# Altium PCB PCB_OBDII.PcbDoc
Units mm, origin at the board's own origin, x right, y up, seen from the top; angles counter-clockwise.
Board outline 98.69 x 84.64 mm, 2 copper layers (F.Cu, B.Cu); 8 components, 39 nets, 74 pads, 0 vias.
Unrouted connection lines stored in the file: 5.
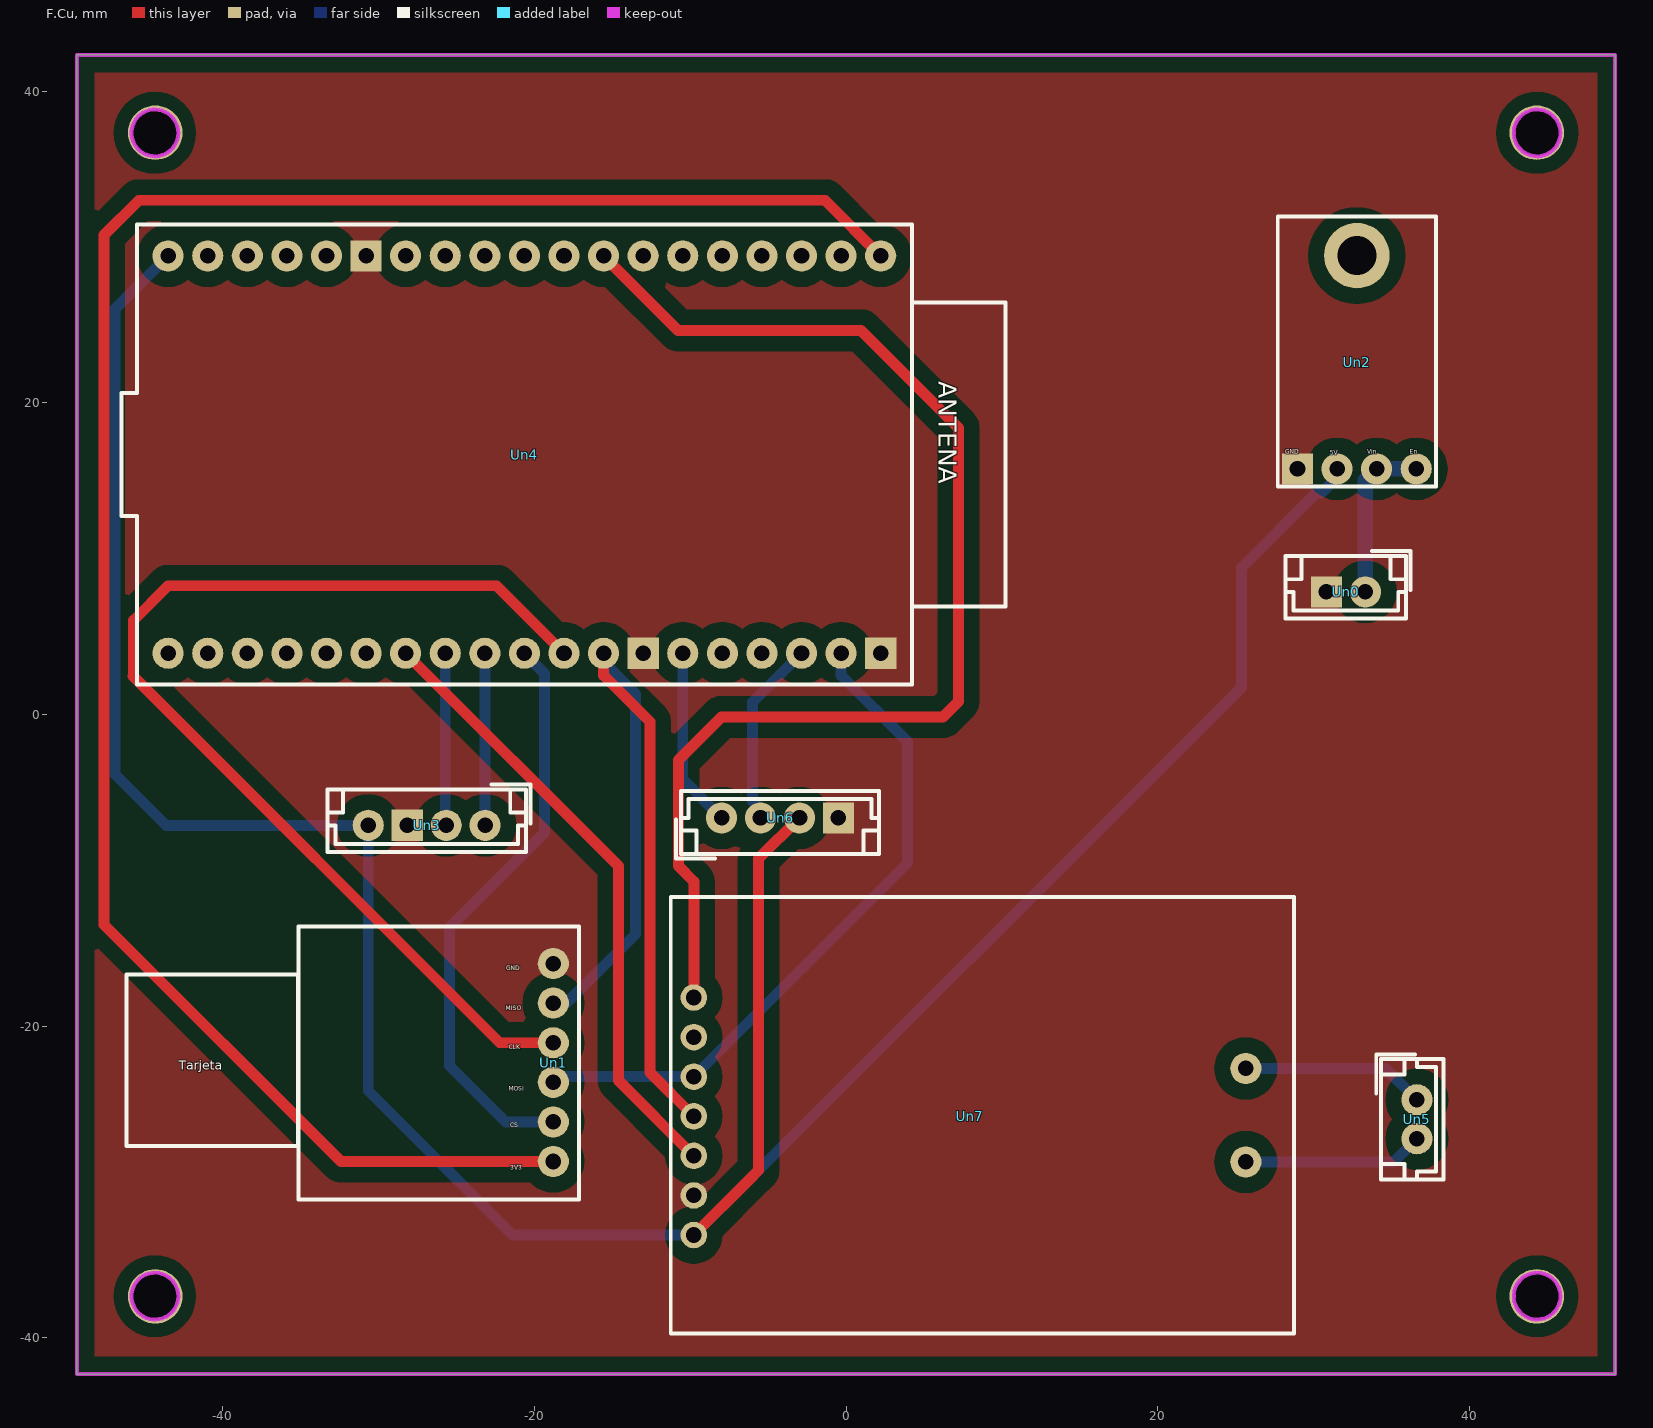
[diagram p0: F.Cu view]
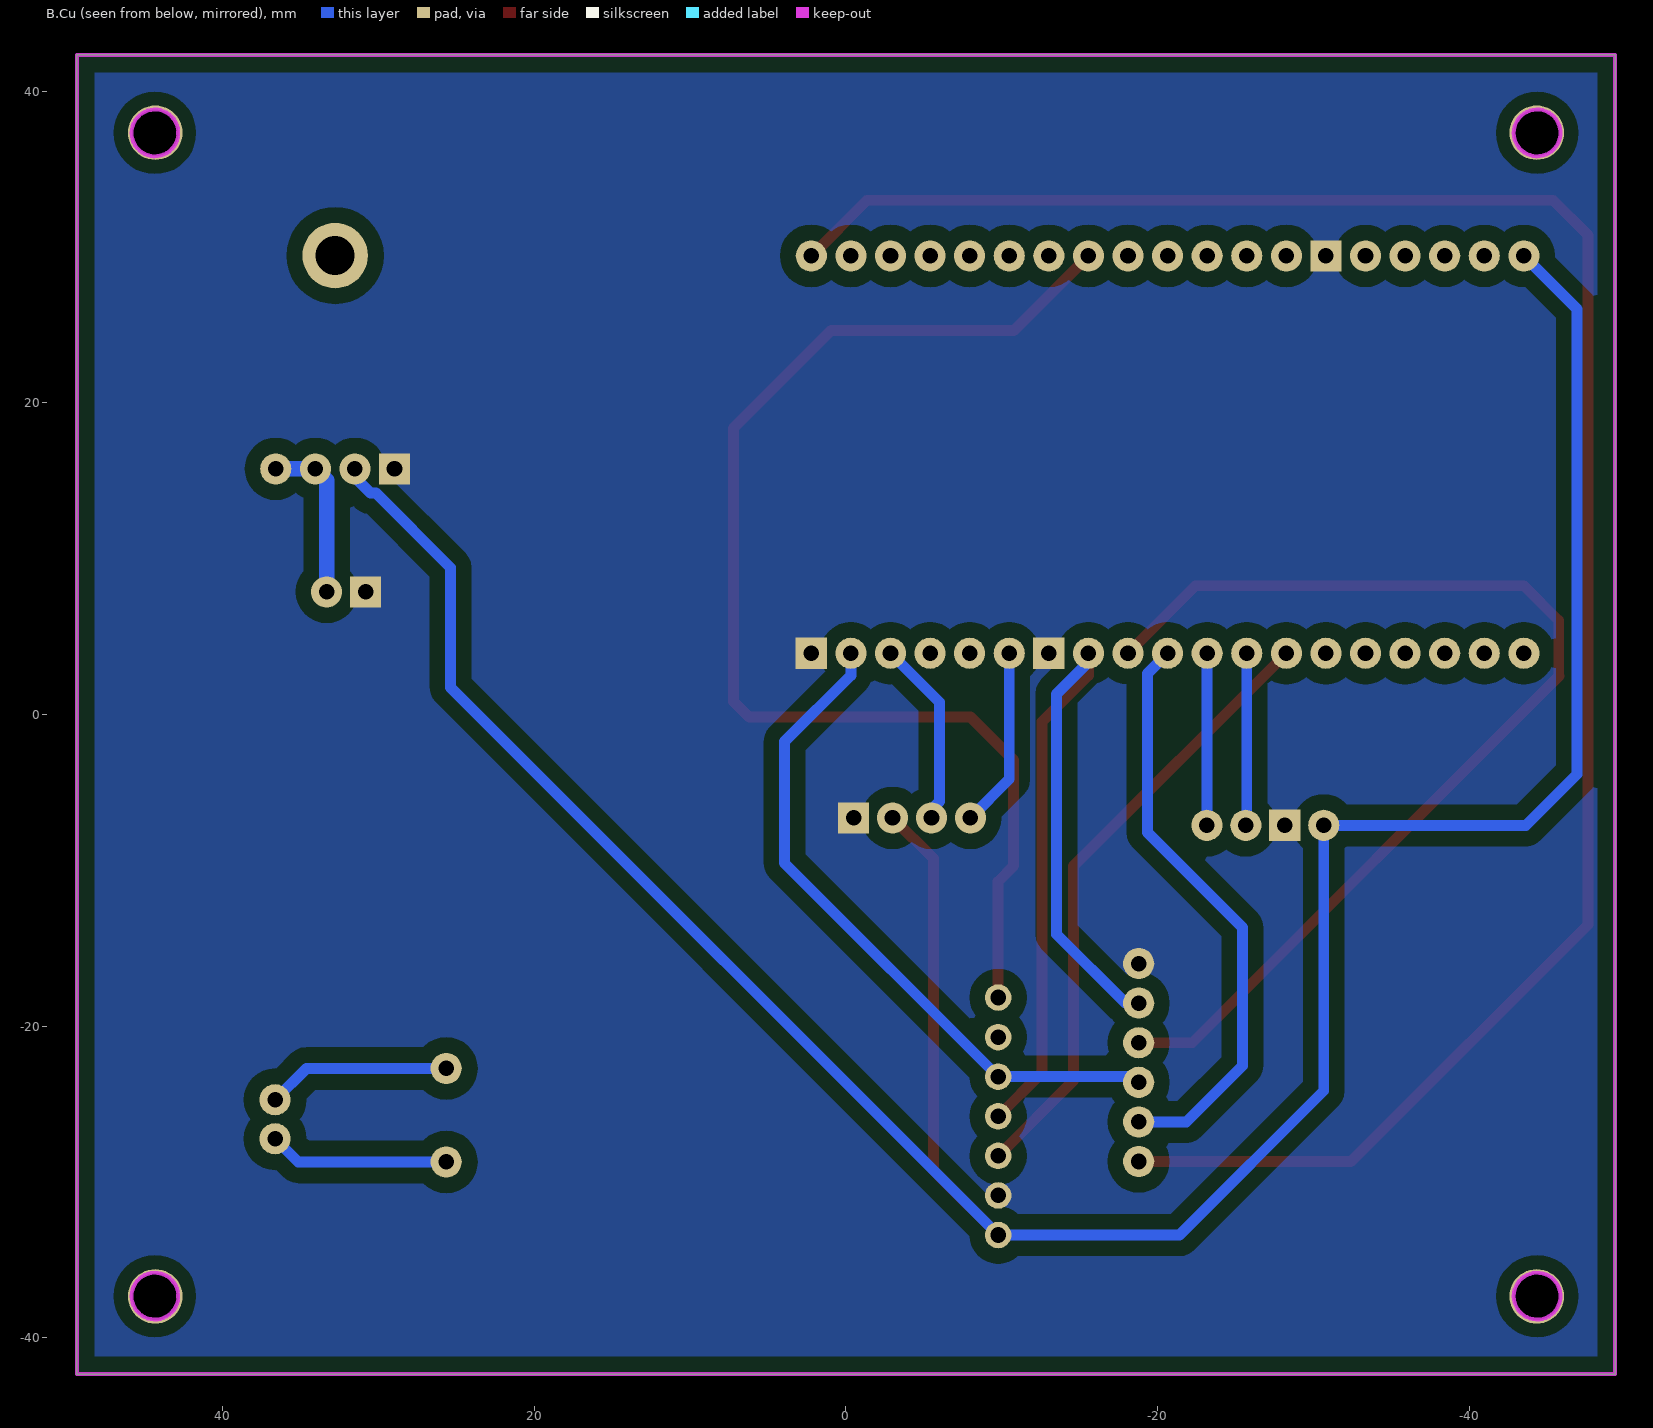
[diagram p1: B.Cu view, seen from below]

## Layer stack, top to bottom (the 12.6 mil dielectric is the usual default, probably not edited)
F.Mask: solder mask 0.0102, Solder Resist, Dk 3.5
F.Cu: signal copper 0.0356
Dielectric 1: dielectric 0.32, FR-4, Dk 4.8
B.Cu: signal copper 0.0356
B.Mask: solder mask 0.0102, Solder Resist, Dk 3.5

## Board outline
49.345,42.32 -49.345,42.32 -49.345,-42.32 49.345,-42.32 49.345,42.32

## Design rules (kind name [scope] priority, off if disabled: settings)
Clearance "Clearence 1_Polygon" [InNamedPolygon('F.Cu-GND') OR InNamedPolygon('B.Cu-GND')] p1: gap=1 ignorepadtopadclearanceinfootprint=FALSE
MinimumSolderMaskSliver [All] p1: minsoldermaskwidth=0
PolygonConnect Polygon_B.Cu-GND_ConnectDirect [IsNamedPolygon('B.Cu-GND')] p1: connectstyle=Direct reliefconductorwidth=0.254 reliefentries=4 polygonreliefangle="90 Angle" airgapwidth=0.254
PolygonConnect Polygon_F.Cu-GND_ConnectDirect [IsNamedPolygon('F.Cu-GND')] p2: connectstyle=Direct reliefconductorwidth=0.254 reliefentries=4 polygonreliefangle="90 Angle" airgapwidth=0.254
RoutingVias [All] p1: holewidth=0.711 width=1.27 viastyle="Through Hole" minholewidth=0.711 minwidth=1.27 maxholewidth=0.711 maxwidth=1.27
SilkToSilkClearance [All] p1: silktosilkclearance=0
SilkToSolderMaskClearance [IsPad] p1: minsilkscreentomaskgap=0 clearancetoexposedcopper=TRUE
SolderMaskExpansion [All] p1: expansion=0.102 istentingtop=FALSE
Width [All] p1: maxlimit=10 minlimit=0.254 preferedwidth=0.254 minimp=50.000000 maximp=50.000000 favimp=50.000000
27 further rules are at their usual default settings.

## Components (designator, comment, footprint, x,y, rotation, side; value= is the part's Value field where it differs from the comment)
Un0 "Comment" JST_EH_B2B-EH-A_1x02_P2.50mm_Vertical#1 33.325,7.87 r180 top value=Conn_01x02
Un1 "Comment" microSD -13.78,-18.77 r0 top value=~
Un2 "Comment" MPM3610_2 24.315,10.53 r0 top value=~
Un3 "Comment" JST_EH_B4B-EH-A_1x04_P2.50mm_Vertical#1 -23.155,-7.11 r180 top value=Conn_01x04
Un4 "Comment" ESP32 -46.105,32.43 r270 top value=~
Un5 "Comment" JST_EH_B2B-EH-A_1x02_P2.50mm_Vertical#2 36.635,-24.72 r270 top value=Conn_01x02
Un6 "Comment" JST_EH_B4B-EH-A_1x04_P2.50mm_Vertical#2 -7.985,-6.63 r0 top value=Conn_01x04
Un7 "Comment" MCP_MODULE -21.245,-1.71 r0 top value=~

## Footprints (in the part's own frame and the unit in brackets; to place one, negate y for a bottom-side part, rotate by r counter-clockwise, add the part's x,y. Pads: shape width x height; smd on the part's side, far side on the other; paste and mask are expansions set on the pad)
ESP32 [mm]
  rrect100% 2x2 hole 1 paste-2539.97 mask+0: 1(3,48.33) 2(3,45.79) 3(3,43.25) 4(3,40.71) 5(3,38.17) 6(3,35.63) 7(3,33.09) 8(3,30.55) 9(3,28.01) 10(3,25.47) 11(3,22.93) 12(3,20.39) 13(3,17.85) 15(3,12.77) 16(3,10.23) 17(3,7.69) 18(3,5.15) 19(3,2.61) 21(28.5,45.79) 22(28.5,43.25) 23(28.5,40.71) 24(28.5,38.17) 25(28.5,35.63) 27(28.5,30.55) 28(28.5,28.01) 29(28.5,25.47) 30(28.5,22.93) 31(28.5,20.39) 32(28.5,17.85) 33(28.5,15.31) 34(28.5,12.77) 35(28.5,10.23) 36(28.5,7.69) 37(28.5,5.15) 38(28.5,2.61)
  rect 2x2 hole 1 paste-2539.97 mask+0: 14(3,15.31) 20(28.5,48.33) 26(28.5,33.09)
  silkscreen extent 1,-0.39 30.5,56.33
JST_EH_B2B-EH-A_1x02_P2.50mm_Vertical#1 [mm]
  rrect100% 2x2 hole 1 paste-2539.97 mask+0: 1(0,0)
  rect 2x2 hole 1 paste-2539.97 mask+0: 2(2.5,0)
  silkscreen extent -2.91,-2.61 5.11,1.71
JST_EH_B2B-EH-A_1x02_P2.50mm_Vertical#2 [mm]
  rrect100% 2x2 hole 1 paste-2539.97 mask+0: 1(0,0) 2(2.5,0)
  silkscreen extent -2.91,-2.61 5.11,1.71
JST_EH_B4B-EH-A_1x04_P2.50mm_Vertical#1 [mm]
  rrect100% 2x2 hole 1 paste-2539.97 mask+0: 1(0,0) 2(2.5,0) 4(7.5,0)
  rect 2x2 hole 1 paste-2539.97 mask+0: 3(5,0)
  silkscreen extent -2.91,-2.61 10.11,1.71
JST_EH_B4B-EH-A_1x04_P2.50mm_Vertical#2 [mm]
  rrect100% 2x2 hole 1 paste-2539.97 mask+0: 1(0,0) 2(2.5,0) 3(5,0)
  rect 2x2 hole 1 paste-2539.97 mask+0: 4(7.5,0)
  silkscreen extent -2.91,-2.61 10.11,1.71
MCP_MODULE [mm]
  rrect100% 1.7x1.7 hole 1 paste-2539.97 mask+0: 1(11.48,-16.45) 2(11.48,-18.99) 3(11.48,-21.53) 4(11.48,-24.07) 5(11.48,-26.61) 6(11.48,-29.15) 7(11.48,-31.69)
  rrect100% 2x2 hole 1 paste-2539.97 mask+0: 8(46.9,-21) 9(46.9,-27)
  silkscreen extent 10,-38 50,-10
microSD [mm]
  rrect100% 2x2 hole 1 paste-2539.97 mask+0: 1(-5,2.79) 2(-5,0.25) 3(-5,-2.29) 4(-5,-4.83) 5(-5,-7.37) 6(-5,-9.91)
  silkscreen extent -32.39,-12.34 -3.35,5.16
MPM3610_2 [mm]
  rect 2x2 hole 1 paste-2539.97 mask+0: 1(4.655,5.23)
  rrect100% 2x2 hole 1 paste-2539.97 mask+0: 2(7.195,5.23) 3(9.735,5.23) 4(12.275,5.23)
  round 4.2 hole 2.5 paste-2539.97 mask+0: 5(8.465,18.92)
  silkscreen extent 3.39,4.1 13.54,21.42

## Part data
Un0 Un5: library part JST_EH_B2B-EH-A_1x02_P2.50mm_Vertical, "JST EH series connector, B2B-EH-A (http://www.jst-mfg.com/product/pdf/eng/eEH.pdf), generated with kicad-footprint-generator"
Un1: library part microSD
Un2: library part MPM3610_2
Un3 Un6: library part JST_EH_B4B-EH-A_1x04_P2.50mm_Vertical, "JST EH series connector, B4B-EH-A (http://www.jst-mfg.com/product/pdf/eng/eEH.pdf), generated with kicad-footprint-generator"
Un4: library part ESP32
Un7: library part MCP_MODULE

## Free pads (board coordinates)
  round 3.5 hole 3: 1(-44.323,-37.338) 1(-44.323,37.338) 1(44.323,-37.338) 1(44.323,37.338)

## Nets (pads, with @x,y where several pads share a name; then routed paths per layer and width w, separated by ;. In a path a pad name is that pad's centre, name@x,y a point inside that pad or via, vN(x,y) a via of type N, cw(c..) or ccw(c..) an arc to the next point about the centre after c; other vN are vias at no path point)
3V3: Un1.6 Un4.1 | length 131.6
  F.Cu w0.7: Un1.6 -32.415,-28.68 -47.605,-13.49 -47.605,30.77 -45.375,33 -1.345,33 Un4.1
5V: Un2.2 Un3.4 Un4.19 Un6.3 Un7.7 | length 190.1
  F.Cu w0.7: Un7.7 -6.225,-29.86 -5.605,-29.24 -5.605,-9.25 Un6.3
  B.Cu w0.7: Un4.19 -46.895,26.03 -46.895,-3.83 -43.615,-7.11 Un3.4 -30.655,-24.14 -21.395,-33.4 Un7.7 25.375,1.74 25.375,9.42 30.165,14.21 30.52,14.21 31.51,15.2 Un2.2
12V: Un0.1 Un2.3 Un2.4 | length 10.7
  B.Cu w1: Un0.1 33.325,15.035 Un2.3 Un2.4
CAN_HIGH: Un5.2 Un7.9 | length 11.6
  B.Cu w0.7: Un7.9 35.145,-28.71 Un5.2
CAN_LOW: Un5.1 Un7.8 | length 11.8
  B.Cu w0.7: Un7.8 34.625,-22.71 Un5.1
CLK: Un1.3 Un4.28 Un7.2 | length 70.6
  F.Cu w0.7: Un1.3 -22.215,-21.06 -45.745,2.47 -45.735,2.48 -45.735,6.02 -43.495,8.26 -22.425,8.26 Un4.28
CS_OBD: Un4.32 Un7.5 | length 39.9
  F.Cu w0.7: Un4.32 -14.595,-9.73 -14.595,-23.49 Un7.5
CS_SD: Un1.5 Un4.29 | length 37.7
  B.Cu w0.7: Un4.29 -19.335,2.63 -19.335,-7.56 -25.435,-13.66 -25.435,-22.54 -21.835,-26.14 Un1.5
GND: pad.1 Un0.2 Un1.1 Un2.1 Un3.3 Un4.14 Un4.20 Un4.26 Un6.4 Un7.6 | length 0.5
  F.Cu w0.7: Un1.1@-19.285,-15.98 Un1.1
INT_OBD: Un4.8 Un7.1 | length 80.1
  F.Cu w0.7: Un4.8 -10.775,24.65 0.965,24.65 7.225,18.39 7.225,0.84 6.235,-0.15 -7.985,-0.15 -10.755,-2.92 -10.755,-9.72 -9.765,-10.71 Un7.1
MISO: Un1.2 Un4.27 Un7.4 | length 58.1
  F.Cu w0.7: Un4.27 -15.555,2.516 -12.575,-0.464 -12.575,-22.97 Un7.4
  B.Cu w0.7: Un1.2 -17.925,-18.52 -13.505,-14.1 -13.505,1.32 -15.555,3.37 Un4.27
MOSI: Un1.4 Un4.21 Un7.3 | length 43.8
  B.Cu w0.7: Un1.4 -18.42,-23.24 Un7.3 3.935,-9.54 3.935,-1.734 -0.315,2.516 Un4.21
RX_IMU: Un3.1 Un4.30 | length 11
  B.Cu w0.7: Un4.30 -23.175,-7.09 Un3.1
SCL: Un4.22 Un6.2 | length 12.1
  B.Cu w0.7: Un6.2 -5.485,-6.1 -5.995,-5.59 -5.995,0.79 Un4.22
SDA: Un4.25 Un6.1 | length 11.6
  B.Cu w0.7: Un4.25 -10.475,-4.14 Un6.1
TX_IMU: Un3.2 Un4.31 | length 11.1
  B.Cu w0.7: Un4.31 -25.715,-7.05 Un3.2
unconnected-(ESP32-0-Pad33): Un4.33
unconnected-(ESP32-2-Pad34): Un4.34
unconnected-(ESP32-12-Pad13): Un4.13
unconnected-(ESP32-13-Pad15): Un4.15
unconnected-(ESP32-14-Pad12): Un4.12
unconnected-(ESP32-15-Pad35): Un4.35
unconnected-(ESP32-25-Pad9): Un4.9
unconnected-(ESP32-26-Pad10): Un4.10
unconnected-(ESP32-27-Pad11): Un4.11
unconnected-(ESP32-32-Pad7): Un4.7
unconnected-(ESP32-34-Pad5): Un4.5
unconnected-(ESP32-35-Pad6): Un4.6
unconnected-(ESP32-CLK-Pad38): Un4.38
unconnected-(ESP32-CMD-Pad18): Un4.18
unconnected-(ESP32-D0-Pad37): Un4.37
unconnected-(ESP32-D1-Pad36): Un4.36
unconnected-(ESP32-D2-Pad16): Un4.16
unconnected-(ESP32-D3-Pad17): Un4.17
unconnected-(ESP32-EN-Pad2): Un4.2
unconnected-(ESP32-RX0-Pad24): Un4.24
unconnected-(ESP32-TX0-Pad23): Un4.23
unconnected-(ESP32-VN-Pad4): Un4.4
unconnected-(ESP32-VP-Pad3): Un4.3
pads on no net: Un2.5

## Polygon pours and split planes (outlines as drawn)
GND on F.Cu "F.Cu-GND" (solid, remove dead copper, pour order 1): -49.335,42.32 49.345,42.31 49.345,-42.29 -49.325,-42.3 -49.355,42.3
GND on B.Cu "B.Cu-GND" (solid, remove dead copper, pour order 2): -49.295,42.25 49.345,42.28 49.295,-42.32 -49.335,-42.24 -49.285,42.28

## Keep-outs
Edge.Cuts:
  circle w0.254: c44.345,37.32 r1.5
  circle w0.254: c-44.345,37.32 r1.5
  circle w0.254: c44.345,-37.32 r1.5
  circle w0.254: c-44.345,-37.32 r1.5
  lines w0: -49.345,-42.32 49.345,-42.32 49.345,42.32 -49.345,42.32 -49.345,-42.32
  lines w0.254: -49.345,-42.32 49.345,-42.32 49.345,42.32 -49.345,42.32 -49.345,-42.32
